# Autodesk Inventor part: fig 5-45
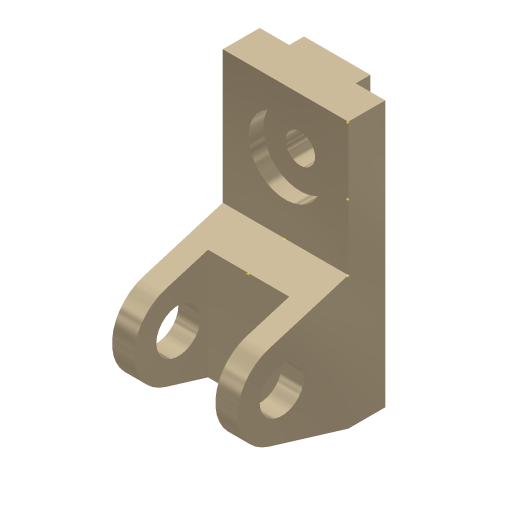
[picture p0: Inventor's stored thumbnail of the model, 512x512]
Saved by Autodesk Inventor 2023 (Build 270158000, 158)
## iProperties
Created: 2001-11
Part Number: fig 5-45
Document SubType Name: Modeling
Designer: Renu Muthoo
Density: 1 g/cm^3
Material: Generic
Appearance: Metal-Titanium (Polished)
Control State: 0
Master: False
Checked Out: False
Shininess: 65.0
Angle Display Precision: 2
Document Length Units: 11269
Document Angle Units: 11279
Document Time Units: 11290
Document Mass Units: 11283
Document Length Units Precision: 3
Document Angle Units Precision: 2
Density: 0.0
Volumn: 0.0
Area: 0.0
PropertySet Name: Model Information
Author: Renu Muthoo
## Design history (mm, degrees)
node "Sketch1"
sketch "Sketch2"
  geometry: L1 (33.257, 104.664)-(33.257, -75.336); L2 (33.257, -75.336)-(8.257, -75.336); L3 (8.257, -75.336)-(-45.451, -59.045); L4 (-45.451, -1.628)-(8.257, 14.664); L5 (8.257, 14.664)-(8.257, 104.664); L6 (8.257, 104.664)-(33.257, 104.664); C1 r 15 at (-36.743, -30.336); A1 r 30 centre (-36.743, -30.336) between (-45.451, -1.628) and (-45.451, -59.045)
  constraints: 12 end point, 2 centre point, 2 equal length, 2 parallel, 2 point on circle, 2 tangent, 1 coincident, 1 perpendicular, 1 vertical
  dimensions: "d0" = 180 distance of L1.start L1.end; "d1" = 30 radius of A1; "d2" = 25 distance of L5.end L1.start; "d3" = 45 distance from line of L2 A1.centre; "d4" = 70 distance from line of L1 A1.centre; "d5" = 30 diameter of C1
extrude "Extrusion1" new body sketch "Sketch2" distance "d6" = 85; taper "d7" = 0 deg
workplane "Work Plane1"
sketch "Sketch3"
  geometry: L1 (15, 62.364)-(70, 62.364); L2 (70, 62.364)-(70, -52.386); L3 (70, -52.386)-(15, -52.386); L4 (15, -52.386)-(15, 62.364); L5 (0, -45)-(0, -28.708) reference
  constraints: 8 end point, 2 parallel, 1 horizontal, 1 perpendicular
  dimensions: "d8" = 55 distance of L1.start L1.end; "d9" = 15 distance between parallel lines of L5 L4
extrude "Extrusion2" cut sketch "Sketch3" distance "d10" = 50; taper "d11" = 0 deg
sketch "Sketch4"
  geometry: L1 (0, 25)-(85, 25) reference; L2 (0, 0)-(0, 25) reference; L3 (20, 25)-(65, 25); L4 (65, 25)-(65, 35); L5 (65, 35)-(20, 35); L6 (20, 35)-(20, 25)
  constraints: 8 end point, 2 parallel, 1 horizontal, 1 perpendicular, 1 point on line
  dimensions: "d12" = 45 distance of L4.end L5.end; "d13" = 10 distance of L3.end L4.end; "d14" = 20 distance between parallel lines of L2 L6
extrude "Extrusion3" join sketch "Sketch4" stored distance "d15" = 50; taper "d16" = 0 deg
sketch "Sketch5"
  geometry: L1 (85, 0)-(85, 90) reference; L2 (0, 90)-(85, 90) reference; 1 further point
  dimensions: "d17" = 42 distance from line of L2 point (42.5, 48); "d18" = 42.5 distance from line of L1 point (42.5, 48)
hole "Hole1" sketch "Sketch5" at (42.5, 48) diameter "d19" = 20; stored, may be unused: countersink angle "d23" = 82 deg, drill point angle "d25" = 118 deg; dims "d20" = 6, "d21" = 50, "d22" = 10, "d24" = 8
workpoint "Work Point1"
workpoint "Work Point2"
workpoint "Work Point3"
workpoint "Work Point4"
workpoint "Work Point5"
body "Solid1"
